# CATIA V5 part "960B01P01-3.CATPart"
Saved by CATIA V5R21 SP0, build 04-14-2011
Part number: 960B01P01-3
Bounding box of the stored display mesh (mm): x -33.4 to 33.4, y 56.85 to 154.7, z -8 to 13.3
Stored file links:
  C:\Users\ALI OZGUN\Desktop\alhan\960B01P01-3.CATPart
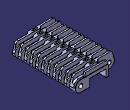
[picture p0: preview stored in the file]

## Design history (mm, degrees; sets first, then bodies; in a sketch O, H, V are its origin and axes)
Body1 (main body)
Body2
  Solid1: solid without history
